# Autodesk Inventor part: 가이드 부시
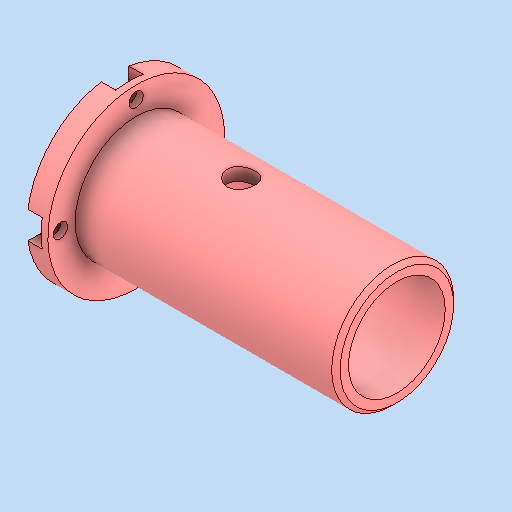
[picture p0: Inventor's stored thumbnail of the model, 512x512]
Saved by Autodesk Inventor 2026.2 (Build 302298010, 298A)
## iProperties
Created: 2026-08
Part Number: 가이드 부시
Material: 강철, 탄소
Document SubType Name: Modeling
Designer: PC-2-06
Density: 7.85 g/cm^3
Appearance: 기본값
Author: jhkim
Sending System: Autodesk Inventor 2027
Preprocessor: ST-DEVELOPER v20.1
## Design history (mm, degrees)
feature "솔리드1"
node "솔리드2"
